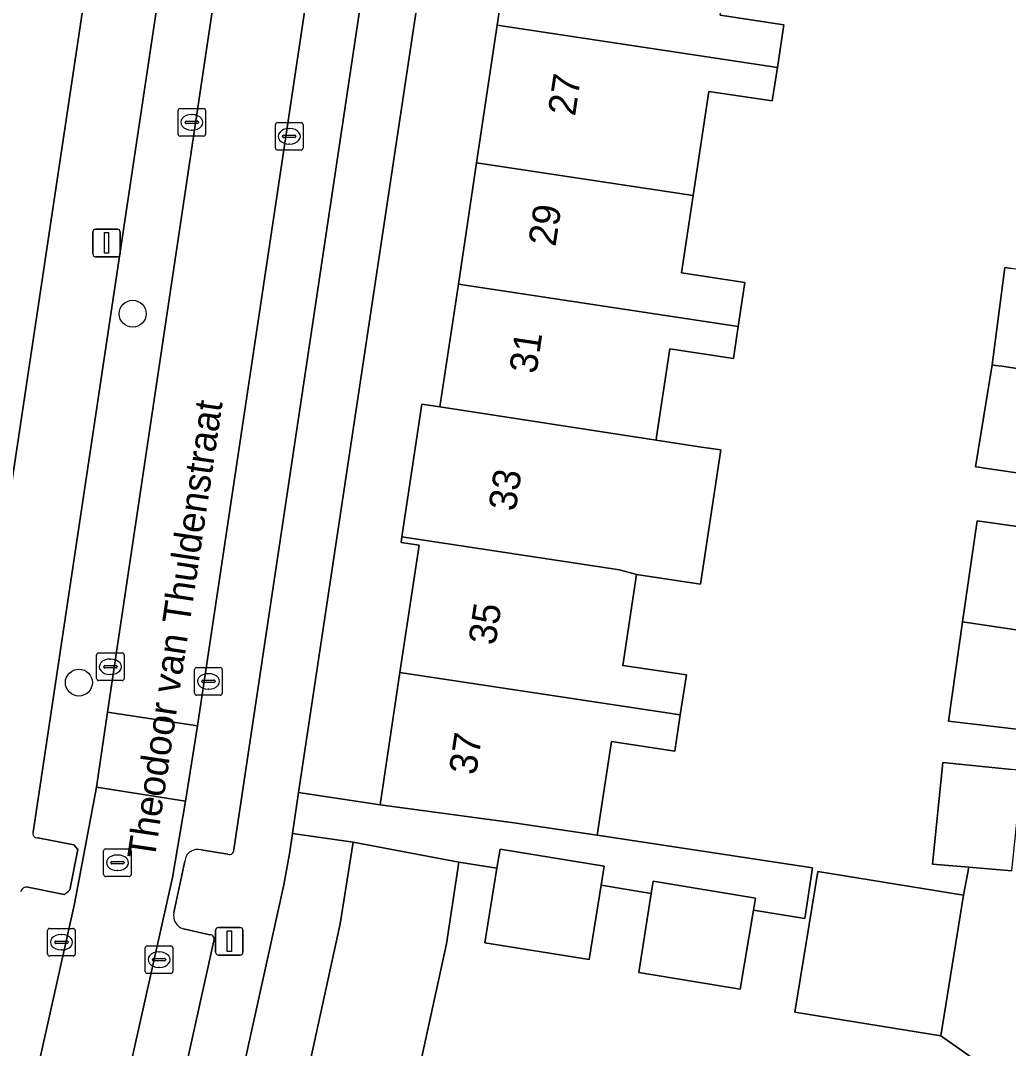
# Model space of a CAD drawing. Extents: x 162172 to 163187, y 382874 to 383685.
# Drawn here: x 162963.31 to 162999.12, y 383137.87 to 383175.15 of the extents above; entities that cross this region are included whole.
import ezdxf

# ---------------------------------------------------------------- set-up
doc = ezdxf.new("R2010")
doc.units = 0
for name, color, linetype in [('IMGEO_Boom', 7, 'Continuous'), ('IMGEO_Erf', 7, 'Continuous'), ('IMGEO_Kolk', 7, 'Continuous'), ('IMGEO_Lichtmast', 7, 'Continuous'), ('IMGEO_Openbare_ruimte_label', 7, 'Continuous'), ('IMGEO_Pand', 7, 'Continuous'), ('IMGEO_Pand_nummerreeks', 7, 'Continuous'), ('IMGEO_Parkeervlak_open', 7, 'Continuous'), ('IMGEO_Rijbaan_lokaal_open', 7, 'Continuous'), ('IMGEO_Rioolput', 7, 'Continuous'), ('IMGEO_Voetpad_open', 7, 'Continuous')]:
    doc.layers.add(name, color=color, linetype=linetype)

msp = doc.modelspace()

# ---------------------------------------------------------------- linework, layer by layer
at = {"layer": 'IMGEO_Boom'}
for centre in [(162967.377, 383164.519), (162965.426, 383151.143)]:
    msp.add_circle(centre, 0.489, dxfattribs=at)
at = {"layer": 'IMGEO_Erf'}
for points in [[(162967.996, 383191.801), (162965.011, 383192.249), (162964.293, 383187.471), (162963.588, 383182.771), (162962.872, 383178.003), (162962.144, 383173.157), (162961.434, 383168.428), (162960.705, 383163.571), (162960.043, 383159.165), (162960.695, 383159.068), (162959.998, 383154.402), (162959.244, 383149.357), (162961.571, 383149.008), (162961.62, 383149.29)], [(162977.863, 383161.237), (162978.516, 383161.139), (162979.184, 383165.588), (162979.845, 383169.991), (162980.594, 383174.981), (162981.333, 383179.903), (162982, 383184.346), (162982.777, 383189.522), (162979.829, 383189.966), (162973.386, 383147.159), (162976.349, 383146.713), (162977.067, 383151.505), (162977.76, 383156.128), (162977.107, 383156.227), (162977.137, 383156.424)]]:
    msp.add_lwpolyline(points, close=True, dxfattribs=at)
for points in [[(162988.679, 383175.346), (162990.981, 383174.999), (162990.747, 383173.447), (162990.564, 383172.238), (162988.262, 383172.585), (162987.692, 383168.806), (162987.269, 383166.005), (162989.57, 383165.658), (162989.328, 383164.056), (162989.153, 383162.897), (162986.852, 383163.244), (162986.371, 383160.061), (162986.352, 383159.938), (162987.998, 383159.686), (162988.703, 383159.578), (162987.967, 383154.71), (162985.644, 383155.061), (162985.147, 383151.766), (162987.448, 383151.419), (162987.229, 383149.97), (162987.031, 383148.658), (162984.73, 383149.005), (162984.216, 383145.603), (162992.024, 383144.424), (162991.747, 383142.59), (162989.884, 383142.893), (162989.405, 383140.018), (162985.73, 383140.631), (162986.178, 383143.497), (162984.355, 383143.793), (162983.921, 383141.097), (162980.149, 383141.705), (162980.584, 383144.407), (162979.199, 383144.633), (162978.752, 383141.667), (162977.651, 383136.621)], [(162999.922, 383158.678), (162998.275, 383158.918), (162998.054, 383158.951), (162997.935, 383158.968), (162998.533, 383162.666), (162998.996, 383166.191), (162999.22, 383166.158)], [(162999.418, 383149.452), (162996.948, 383149.737), (162997.464, 383153.351), (162997.988, 383157.014), (162999.626, 383156.78)], [(162998.582, 383136.984), (162996.669, 383138.332), (162991.387, 383139.192), (162992.218, 383144.294), (162997.499, 383143.436), (162997.686, 383144.443), (162996.369, 383144.553), (162996.749, 383148.244)], [(162996.749, 383148.244), (162999.249, 383147.991)], [(162973.823, 383137.457), (162974.899, 383142.39), (162975.371, 383145.354), (162973.166, 383145.668), (162973.072, 383145.005), (162972.855, 383143.81), (162967.919, 383121.404)]]:
    msp.add_lwpolyline(points, dxfattribs=at)
at = {"layer": 'IMGEO_Kolk'}
for p, q in [((162969.095, 383171.962), (162969.947, 383171.962)), ((162969.02, 383171.036), (162969.02, 383171.888)), ((162969.508, 383171.742), (162969.533, 383171.742)), ((162970.021, 383171.888), (162970.021, 383171.036)), ((162969.279, 383171.456), (162969.279, 383171.468)), ((162969.717, 383171.419), (162969.319, 383171.419)), ((162969.322, 383171.505), (162969.72, 383171.505)), ((162969.531, 383171.182), (162969.506, 383171.182)), ((162969.763, 383171.468), (162969.763, 383171.456)), ((162972.553, 383170.529), (162972.553, 383171.381)), ((162972.628, 383171.455), (162973.48, 383171.455)), ((162973.041, 383171.235), (162973.066, 383171.235)), ((162973.554, 383171.381), (162973.554, 383170.529)), ((162969.947, 383170.962), (162969.095, 383170.962)), ((162972.812, 383170.949), (162972.812, 383170.961)), ((162973.25, 383170.912), (162972.852, 383170.912)), ((162972.855, 383170.998), (162973.253, 383170.998)), ((162973.296, 383170.961), (162973.296, 383170.949)), ((162973.48, 383170.455), (162972.628, 383170.455)), ((162973.064, 383170.675), (162973.039, 383170.675)), ((162966.067, 383151.29), (162966.067, 383152.142)), ((162966.142, 383152.216), (162966.994, 383152.216)), ((162967.068, 383152.142), (162967.068, 383151.29)), ((162966.555, 383151.996), (162966.58, 383151.996)), ((162966.326, 383151.71), (162966.326, 383151.722)), ((162966.764, 383151.673), (162966.366, 383151.673)), ((162966.369, 383151.759), (162966.767, 383151.759)), ((162966.578, 383151.436), (162966.553, 383151.436)), ((162966.81, 383151.722), (162966.81, 383151.71)), ((162969.623, 383150.76), (162969.623, 383151.612)), ((162969.698, 383151.686), (162970.55, 383151.686)), ((162970.111, 383151.466), (162970.136, 383151.466)), ((162970.624, 383151.612), (162970.624, 383150.76)), ((162966.994, 383151.216), (162966.142, 383151.216)), ((162969.882, 383151.18), (162969.882, 383151.192)), ((162970.32, 383151.143), (162969.922, 383151.143)), ((162969.925, 383151.229), (162970.323, 383151.229)), ((162970.366, 383151.192), (162970.366, 383151.18)), ((162970.55, 383150.686), (162969.698, 383150.686)), ((162970.134, 383150.906), (162970.109, 383150.906)), ((162964.293, 383141.3), (162964.293, 383142.152)), ((162964.368, 383142.226), (162965.22, 383142.226)), ((162965.294, 383142.152), (162965.294, 383141.3)), ((162964.552, 383141.72), (162964.552, 383141.732)), ((162964.595, 383141.769), (162964.993, 383141.769)), ((162964.781, 383142.006), (162964.806, 383142.006)), ((162965.036, 383141.732), (162965.036, 383141.72)), ((162964.99, 383141.683), (162964.592, 383141.683)), ((162964.804, 383141.446), (162964.779, 383141.446)), ((162967.832, 383140.667), (162967.832, 383141.519)), ((162967.907, 383141.593), (162968.759, 383141.593)), ((162968.32, 383141.373), (162968.345, 383141.373)), ((162968.833, 383141.519), (162968.833, 383140.667)), ((162965.22, 383141.226), (162964.368, 383141.226)), ((162968.091, 383141.087), (162968.091, 383141.099)), ((162968.529, 383141.05), (162968.131, 383141.05)), ((162968.134, 383141.136), (162968.532, 383141.136)), ((162968.575, 383141.099), (162968.575, 383141.087)), ((162968.759, 383140.593), (162967.907, 383140.593)), ((162968.343, 383140.813), (162968.318, 383140.813))]:
    msp.add_line(p, q, dxfattribs=at)
for points in [[(162969.095, 383171.962), (162969.947, 383171.962)], [(162969.02, 383171.036), (162969.02, 383171.888)], [(162970.021, 383171.888), (162970.021, 383171.036)], [(162972.553, 383170.529), (162972.553, 383171.381)], [(162972.628, 383171.455), (162973.48, 383171.455)], [(162973.554, 383171.381), (162973.554, 383170.529)], [(162969.947, 383170.962), (162969.095, 383170.962)], [(162973.48, 383170.455), (162972.628, 383170.455)], [(162966.067, 383151.29), (162966.067, 383152.142)], [(162966.142, 383152.216), (162966.994, 383152.216)], [(162967.068, 383152.142), (162967.068, 383151.29)], [(162969.623, 383150.76), (162969.623, 383151.612)], [(162969.698, 383151.686), (162970.55, 383151.686)], [(162970.624, 383151.612), (162970.624, 383150.76)], [(162966.994, 383151.216), (162966.142, 383151.216)], [(162970.55, 383150.686), (162969.698, 383150.686)], [(162964.293, 383141.3), (162964.293, 383142.152)], [(162964.368, 383142.226), (162965.22, 383142.226)], [(162965.294, 383142.152), (162965.294, 383141.3)], [(162967.832, 383140.667), (162967.832, 383141.519)], [(162967.907, 383141.593), (162968.759, 383141.593)], [(162968.833, 383141.519), (162968.833, 383140.667)], [(162965.22, 383141.226), (162964.368, 383141.226)], [(162968.759, 383140.593), (162967.907, 383140.593)]]:
    msp.add_lwpolyline(points, dxfattribs=at)
for centre, radius, start, end in [((162969.097, 383171.886), 0.0765, 91.552, 178.448), ((162969.097, 383171.886), 0.0765, 91.552, 178.448), ((162969.945, 383171.886), 0.0765, 1.552, 88.448), ((162969.945, 383171.886), 0.0765, 1.552, 88.448), ((162969.319, 383171.465), 0.0403, 85.8775, 175.7526), ((162969.316, 383171.455), 0.0366, 178.938, 274.7102), ((162969.72, 383171.462), 0.043, 264.8664, 352.4533), ((162969.724, 383171.467), 0.0386, 1.7309, 96.639), ((162972.63, 383171.379), 0.0765, 91.552, 178.448), ((162972.63, 383171.379), 0.0765, 91.552, 178.448), ((162973.478, 383171.379), 0.0765, 1.552, 88.448), ((162973.478, 383171.379), 0.0765, 1.552, 88.448), ((162969.097, 383171.038), 0.0765, 181.552, 268.448), ((162969.097, 383171.038), 0.0765, 181.552, 268.448), ((162969.945, 383171.038), 0.0765, 271.552, 358.448), ((162969.945, 383171.038), 0.0765, 271.552, 358.448), ((162972.852, 383170.958), 0.0403, 85.8775, 175.7526), ((162972.849, 383170.948), 0.0366, 178.938, 274.7102), ((162973.253, 383170.955), 0.043, 264.8664, 352.4533), ((162973.257, 383170.96), 0.0386, 1.7309, 96.639), ((162972.63, 383170.531), 0.0765, 181.552, 268.448), ((162972.63, 383170.531), 0.0765, 181.552, 268.448), ((162973.478, 383170.531), 0.0765, 271.552, 358.448), ((162973.478, 383170.531), 0.0765, 271.552, 358.448), ((162966.144, 383152.14), 0.0765, 91.552, 178.448), ((162966.144, 383152.14), 0.0765, 91.552, 178.448), ((162966.992, 383152.14), 0.0765, 1.552, 88.448), ((162966.992, 383152.14), 0.0765, 1.552, 88.448), ((162966.366, 383151.719), 0.0403, 85.8775, 175.7526), ((162966.363, 383151.709), 0.0366, 178.938, 274.7102), ((162966.767, 383151.716), 0.043, 264.8664, 352.4533), ((162966.771, 383151.721), 0.0386, 1.7309, 96.639), ((162969.7, 383151.61), 0.0765, 91.552, 178.448), ((162969.7, 383151.61), 0.0765, 91.552, 178.448), ((162970.548, 383151.61), 0.0765, 1.552, 88.448), ((162970.548, 383151.61), 0.0765, 1.552, 88.448), ((162966.144, 383151.292), 0.0765, 181.552, 268.448), ((162966.144, 383151.292), 0.0765, 181.552, 268.448), ((162966.992, 383151.292), 0.0765, 271.552, 358.448), ((162966.992, 383151.292), 0.0765, 271.552, 358.448), ((162969.922, 383151.189), 0.0403, 85.8775, 175.7526), ((162969.919, 383151.179), 0.0366, 178.938, 274.7102), ((162970.323, 383151.186), 0.043, 264.8664, 352.4533), ((162970.327, 383151.191), 0.0386, 1.7309, 96.639), ((162969.7, 383150.762), 0.0765, 181.552, 268.448), ((162969.7, 383150.762), 0.0765, 181.552, 268.448), ((162970.548, 383150.762), 0.0765, 271.552, 358.448), ((162970.548, 383150.762), 0.0765, 271.552, 358.448), ((162964.37, 383142.15), 0.0765, 91.552, 178.448), ((162964.37, 383142.15), 0.0765, 91.552, 178.448), ((162965.218, 383142.15), 0.0765, 1.552, 88.448), ((162965.218, 383142.15), 0.0765, 1.552, 88.448), ((162964.592, 383141.729), 0.0403, 85.8775, 175.7526), ((162964.589, 383141.719), 0.0366, 178.938, 274.7102), ((162964.993, 383141.726), 0.043, 264.8664, 352.4533), ((162964.997, 383141.731), 0.0386, 1.7309, 96.639), ((162967.909, 383141.517), 0.0765, 91.552, 178.448), ((162967.909, 383141.517), 0.0765, 91.552, 178.448), ((162968.757, 383141.517), 0.0765, 1.552, 88.448), ((162968.757, 383141.517), 0.0765, 1.552, 88.448), ((162964.37, 383141.302), 0.0765, 181.552, 268.448), ((162964.37, 383141.302), 0.0765, 181.552, 268.448), ((162965.218, 383141.302), 0.0765, 271.552, 358.448), ((162965.218, 383141.302), 0.0765, 271.552, 358.448), ((162968.131, 383141.096), 0.0403, 85.8775, 175.7526), ((162968.128, 383141.086), 0.0366, 178.938, 274.7102), ((162968.532, 383141.093), 0.043, 264.8664, 352.4533), ((162968.536, 383141.098), 0.0386, 1.7309, 96.639), ((162967.909, 383140.669), 0.0765, 181.552, 268.448), ((162967.909, 383140.669), 0.0765, 181.552, 268.448), ((162968.757, 383140.669), 0.0765, 271.552, 358.448), ((162968.757, 383140.669), 0.0765, 271.552, 358.448)]:
    msp.add_arc(centre, radius, start, end, dxfattribs=at)
for centre, major_axis, ratio, start_param, end_param in [((162969.507, 383171.462), (-0.387, 0.002), 0.722429, 4.712389, 7.853982), ((162969.532, 383171.462), (-0.39, 0.002), 0.717154, 1.570796, 4.712389), ((162973.04, 383170.955), (-0.387, 0.002), 0.722429, 4.712389, 7.853982), ((162973.065, 383170.955), (-0.39, 0.002), 0.717154, 1.570796, 4.712389), ((162966.554, 383151.716), (-0.387, 0.002), 0.722429, 4.712389, 7.853982), ((162966.579, 383151.716), (-0.39, 0.002), 0.717154, 1.570796, 4.712389), ((162970.11, 383151.186), (-0.387, 0.002), 0.722429, 4.712389, 7.853982), ((162970.135, 383151.186), (-0.39, 0.002), 0.717154, 1.570796, 4.712389), ((162964.78, 383141.726), (-0.387, 0.002), 0.722429, 4.712389, 7.853982), ((162964.805, 383141.726), (-0.39, 0.002), 0.717154, 1.570796, 4.712389), ((162968.319, 383141.093), (-0.387, 0.002), 0.722429, 4.712389, 7.853982), ((162968.344, 383141.093), (-0.39, 0.002), 0.717154, 1.570796, 4.712389)]:
    msp.add_ellipse(centre, major_axis=major_axis, ratio=ratio, start_param=start_param, end_param=end_param, dxfattribs=at)
at = {"layer": 'IMGEO_Lichtmast'}
for p, q in [((162965.932, 383166.687), (162965.932, 383167.487)), ((162965.932, 383167.487), (162965.932, 383166.687)), ((162966.032, 383167.587), (162966.822, 383167.587)), ((162966.822, 383167.587), (162966.032, 383167.587)), ((162966.922, 383167.487), (162966.922, 383166.687)), ((162966.922, 383166.687), (162966.922, 383167.487)), ((162966.822, 383166.587), (162966.032, 383166.587)), ((162966.032, 383166.587), (162966.822, 383166.587)), ((162970.383, 383141.359), (162970.383, 383142.159)), ((162970.383, 383142.159), (162970.383, 383141.359)), ((162970.483, 383142.259), (162971.273, 383142.259)), ((162971.273, 383142.259), (162970.483, 383142.259)), ((162971.373, 383142.159), (162971.373, 383141.359)), ((162971.373, 383141.359), (162971.373, 383142.159)), ((162971.273, 383141.259), (162970.483, 383141.259)), ((162970.483, 383141.259), (162971.273, 383141.259))]:
    msp.add_line(p, q, dxfattribs=at)
for points in [[(162966.352, 383167.462), (162966.502, 383167.462), (162966.502, 383166.712), (162966.352, 383166.712), (162966.352, 383167.462)], [(162970.803, 383142.134), (162970.953, 383142.134), (162970.953, 383141.384), (162970.803, 383141.384), (162970.803, 383142.134)]]:
    msp.add_lwpolyline(points, dxfattribs=at)
for centre, start, end in [((162966.032, 383167.487), 90, 180), ((162966.032, 383167.487), 90, 180), ((162966.822, 383167.487), 0, 90), ((162966.822, 383167.487), 360, 90), ((162966.032, 383166.687), 180, 270), ((162966.032, 383166.687), 180, 270), ((162966.822, 383166.687), 270, 0), ((162966.822, 383166.687), 270, 0), ((162970.483, 383142.159), 90, 180), ((162970.483, 383142.159), 90, 180), ((162971.273, 383142.159), 0, 90), ((162971.273, 383142.159), 360, 90), ((162970.483, 383141.359), 180, 270), ((162970.483, 383141.359), 180, 270), ((162971.273, 383141.359), 270, 0), ((162971.273, 383141.359), 270, 0)]:
    msp.add_arc(centre, 0.1, start, end, dxfattribs=at)
at = {"layer": 'IMGEO_Pand'}
for points in [[(162981.333, 383179.903), (162980.594, 383174.981), (162990.747, 383173.447), (162990.981, 383174.999), (162988.679, 383175.346), (162989.188, 383178.716)], [(162987.692, 383168.806), (162988.262, 383172.585), (162990.564, 383172.238), (162990.747, 383173.447), (162980.594, 383174.981), (162979.845, 383169.991)], [(162989.328, 383164.056), (162989.57, 383165.658), (162987.269, 383166.005), (162987.692, 383168.806), (162979.845, 383169.991), (162979.184, 383165.588)], [(163002.136, 383165.737), (162999.22, 383166.158), (162998.996, 383166.191), (162998.533, 383162.666), (162998.652, 383162.648), (162998.881, 383162.613), (163001.565, 383162.208), (163002.089, 383165.451)], [(162986.852, 383163.244), (162989.153, 383162.897), (162989.328, 383164.056), (162979.184, 383165.588), (162978.516, 383161.139), (162986.352, 383159.938), (162986.371, 383160.061)], [(163001.565, 383162.208), (162998.881, 383162.613), (162998.652, 383162.648), (162998.533, 383162.666), (162997.935, 383158.968), (162998.054, 383158.951), (162998.275, 383158.918), (162999.922, 383158.678), (163000.969, 383158.526)], [(162986.352, 383159.938), (162978.516, 383161.139), (162977.863, 383161.237), (162977.137, 383156.424), (162985.029, 383155.231), (162985.644, 383155.061), (162987.967, 383154.71), (162988.703, 383159.578), (162987.998, 383159.686)], [(163000.902, 383156.597), (162999.626, 383156.78), (162997.988, 383157.014), (162997.464, 383153.351), (163000.375, 383152.911)], [(162987.229, 383149.97), (162987.448, 383151.419), (162985.147, 383151.766), (162985.644, 383155.061), (162985.029, 383155.231), (162977.137, 383156.424), (162977.107, 383156.227), (162977.76, 383156.128), (162977.067, 383151.505)], [(163000.375, 383152.911), (162997.464, 383153.351), (162996.948, 383149.737), (162999.418, 383149.452), (162999.873, 383149.399)], [(162987.229, 383149.97), (162977.067, 383151.505), (162976.349, 383146.713), (162981.195, 383146.059), (162984.216, 383145.603), (162984.73, 383149.005), (162987.031, 383148.658)], [(162999.621, 383147.953), (162999.249, 383147.991), (162996.749, 383148.244), (162996.369, 383144.553), (162997.686, 383144.443), (162999.246, 383144.312)], [(162975.371, 383145.354), (162974.899, 383142.39), (162973.823, 383137.457), (162977.651, 383136.621), (162978.752, 383141.667), (162979.199, 383144.633)], [(162984.355, 383143.793), (162984.467, 383144.487), (162980.695, 383145.095), (162980.584, 383144.407), (162980.149, 383141.705), (162983.921, 383141.097)], [(162989.884, 383142.893), (162989.956, 383143.322), (162986.247, 383143.94), (162986.178, 383143.497), (162985.73, 383140.631), (162989.405, 383140.018)], [(162997.499, 383143.436), (162992.218, 383144.294), (162991.387, 383139.192), (162996.669, 383138.332)]]:
    msp.add_lwpolyline(points, close=True, dxfattribs=at)
at = {"layer": 'IMGEO_Parkeervlak_open'}
for points in [[(162961.044, 383124.266), (162965.268, 383143.121), (162966.059, 383147.348), (162966.461, 383150.066), (162972.803, 383192.564), (162973.231, 383195.286), (162979.423, 383236.668), (162979.85, 383239.428), (162984.085, 383267.824)], [(162987.312, 383267.33), (162983.074, 383238.918), (162982.697, 383236.132), (162976.489, 383194.817), (162976.089, 383192.091), (162969.728, 383149.579), (162969.289, 383146.836), (162968.82, 383144.072), (162964.054, 383122.788)], [(162977.839, 383239.594), (162963.769, 383145.719)], [(162971.04, 383145.083), (162984.32, 383233.732)], [(162963.938, 383145.513), (162965.248, 383145.259), (162965.389, 383145.085), (162965.1, 383143.628)], [(162969.859, 383145.075), (162970.829, 383144.917)], [(162968.871, 383142.809), (162969.266, 383144.664)], [(162964.89, 383143.457), (162963.576, 383143.726)], [(162970.179, 383141.998), (162969.218, 383142.208)], [(162966.118, 383122.769), (162970.319, 383141.775)]]:
    msp.add_lwpolyline(points, dxfattribs=at)
for centre, radius, start, end in [((162963.912, 383145.664), 0.153, 158.7637, 279.9664), ((162969.733, 383144.624), 0.468, 74.3598, 175.0908), ((162970.884, 383145.065), 0.157, 249.7284, 6.658), ((162963.536, 383143.492), 0.237, 80.2276, 160.6086), ((162964.145, 383144.587), 1.353, 303.4135, 314.8974), ((162969.359, 383142.69), 0.502, 166.3099, 253.6919), ((162970.178, 383141.842), 0.156, 334.6832, 89.5583)]:
    msp.add_arc(centre, radius, start, end, dxfattribs=at)
at = {"layer": 'IMGEO_Rijbaan_lokaal_open'}
for points in [[(162966.461, 383150.066), (162969.728, 383149.579), (162976.089, 383192.091), (162972.803, 383192.564)], [(162966.059, 383147.348), (162969.289, 383146.836), (162969.728, 383149.579), (162966.461, 383150.066)], [(162960.241, 383120.675), (162963.424, 383120.03), (162964.054, 383122.788), (162968.82, 383144.072), (162969.289, 383146.836), (162966.059, 383147.348), (162965.268, 383143.121), (162961.044, 383124.266)]]:
    msp.add_lwpolyline(points, close=True, dxfattribs=at)
at = {"layer": 'IMGEO_Rioolput'}
for p, q in [((162966.398, 383145.109), (162967.25, 383145.109)), ((162966.323, 383144.183), (162966.323, 383145.035)), ((162966.811, 383144.889), (162966.836, 383144.889)), ((162967.324, 383145.035), (162967.324, 383144.183)), ((162966.582, 383144.603), (162966.582, 383144.615)), ((162967.02, 383144.566), (162966.622, 383144.566)), ((162966.625, 383144.652), (162967.023, 383144.652)), ((162966.834, 383144.329), (162966.809, 383144.329)), ((162967.066, 383144.615), (162967.066, 383144.603)), ((162967.25, 383144.109), (162966.398, 383144.109))]:
    msp.add_line(p, q, dxfattribs=at)
for points in [[(162966.398, 383145.109), (162967.25, 383145.109)], [(162966.323, 383144.183), (162966.323, 383145.035)], [(162967.324, 383145.035), (162967.324, 383144.183)], [(162967.25, 383144.109), (162966.398, 383144.109)]]:
    msp.add_lwpolyline(points, dxfattribs=at)
for centre, radius, start, end in [((162966.4, 383145.033), 0.0765, 91.552, 178.448), ((162966.4, 383145.033), 0.0765, 91.552, 178.448), ((162967.248, 383145.033), 0.0765, 1.552, 88.448), ((162967.248, 383145.033), 0.0765, 1.552, 88.448), ((162966.622, 383144.612), 0.0403, 85.8775, 175.7526), ((162966.619, 383144.602), 0.0366, 178.938, 274.7102), ((162967.023, 383144.609), 0.043, 264.8664, 352.4533), ((162967.027, 383144.614), 0.0386, 1.7309, 96.639), ((162966.4, 383144.185), 0.0765, 181.552, 268.448), ((162966.4, 383144.185), 0.0765, 181.552, 268.448), ((162967.248, 383144.185), 0.0765, 271.552, 358.448), ((162967.248, 383144.185), 0.0765, 271.552, 358.448)]:
    msp.add_arc(centre, radius, start, end, dxfattribs=at)
for centre, major_axis, ratio, start_param, end_param in [((162966.81, 383144.609), (-0.387, 0.002), 0.722429, 4.712389, 7.853982), ((162966.835, 383144.609), (-0.39, 0.002), 0.717154, 1.570796, 4.712389)]:
    msp.add_ellipse(centre, major_axis=major_axis, ratio=ratio, start_param=start_param, end_param=end_param, dxfattribs=at)
at = {"layer": 'IMGEO_Voetpad_open'}
for points in [[(162978.175, 383241.837), (162982.044, 383267.498), (162979.454, 383268.227), (162978.458, 383261.497), (162977.859, 383257.448), (162975.94, 383244.627), (162975.499, 383241.819), (162975.456, 383241.535), (162975.284, 383240.385), (162968.157, 383192.874), (162967.996, 383191.801), (162961.62, 383149.29), (162961.571, 383149.008), (162961.307, 383147.483), (162961.288, 383147.372), (162960.945, 383145.438), (162956.262, 383123.982), (162952.155, 383121.467), (162959.964, 383119.516), (162960.241, 383120.675), (162961.044, 383124.266)], [(162967.919, 383121.404), (162972.855, 383143.81), (162973.072, 383145.005), (162973.166, 383145.668), (162973.249, 383146.248), (162973.386, 383147.159), (162979.829, 383189.966), (162980.052, 383191.449), (162987.141, 383238.55), (162987.353, 383239.958), (162987.775, 383242.751), (162988.429, 383247.078), (162990.26, 383259.714), (162991.274, 383266.454), (162991.407, 383267.283)], [(162963.769, 383145.719), (162977.839, 383239.594)], [(162984.32, 383233.732), (162971.04, 383145.083)], [(162965.1, 383143.628), (162965.389, 383145.085), (162965.248, 383145.259), (162963.938, 383145.513)], [(162970.829, 383144.917), (162969.859, 383145.075)], [(162969.266, 383144.664), (162968.871, 383142.809)], [(162999.246, 383144.312), (162997.686, 383144.443), (162997.499, 383143.436), (162996.669, 383138.332), (162998.582, 383136.984)], [(162963.576, 383143.726), (162964.89, 383143.457)], [(162969.218, 383142.208), (162970.179, 383141.998)], [(162970.319, 383141.775), (162966.118, 383122.769)]]:
    msp.add_lwpolyline(points, dxfattribs=at)
msp.add_lwpolyline([(162981.195, 383146.059), (162976.349, 383146.713), (162973.386, 383147.159), (162973.249, 383146.248), (162973.166, 383145.668), (162975.371, 383145.354), (162979.199, 383144.633), (162980.584, 383144.407), (162980.695, 383145.095), (162984.467, 383144.487), (162984.355, 383143.793), (162986.178, 383143.497), (162986.247, 383143.94), (162989.956, 383143.322), (162989.884, 383142.893), (162991.747, 383142.59), (162992.024, 383144.424), (162984.216, 383145.603)], close=True, dxfattribs=at)
for centre, radius, start, end in [((162963.912, 383145.664), 0.153, 158.7637, 279.9664), ((162969.733, 383144.624), 0.468, 74.3598, 175.0908), ((162970.884, 383145.065), 0.157, 249.7284, 6.658), ((162963.536, 383143.492), 0.237, 80.2276, 160.6086), ((162964.145, 383144.587), 1.353, 303.4135, 314.8974), ((162969.359, 383142.69), 0.502, 166.3099, 253.6919), ((162970.178, 383141.842), 0.156, 334.6832, 89.5583)]:
    msp.add_arc(centre, radius, start, end, dxfattribs=at)

# ---------------------------------------------------------------- texts
at = {"layer": 'IMGEO_Openbare_ruimte_label'}
msp.add_text('Theodoor van Thuldenstraat', height=1, rotation=81.5457, dxfattribs=at).set_placement((162968.167, 383144.68))
msp.add_text('Theodoor van Thuldenstraat', height=1, rotation=81.5457, dxfattribs=at).set_placement((162968.167, 383144.68))
at = {"layer": 'IMGEO_Pand_nummerreeks'}
for s, rotation, p in [('27', 81.4619, (162983.412, 383171.661)), ('29', 81.4619, (162982.702, 383166.93)), ('31', 81.4631, (162982.009, 383162.312)), ('33', 81.423, (162981.258, 383157.327)), ('35', 81.4767, (162980.529, 383152.47)), ('37', 81.4767, (162979.824, 383147.763))]:
    msp.add_text(s, height=1, rotation=rotation, dxfattribs=at).set_placement(p)

doc.saveas('drawing.dxf')
